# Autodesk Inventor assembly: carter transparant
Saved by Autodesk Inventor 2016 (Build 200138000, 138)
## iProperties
Created: 2013-10
Part Number: carter transparant
Material: Générique
Document SubType Name: Assembly
Designer: Bruno
Author: Bruno
Sending System: SolidWorks 2013
Last Author: christophe
Last Saved: 2014-02-15
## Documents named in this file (3)
- D:\Cours\Systèmes SI\Robot Haptique\Documentations_pedagogique\Modèle solidworks\Réel\carter transparant.iam
- D:\Cours\Systèmes SI\Robot Haptique\Documentations_pedagogique\Modèle solidworks\Réel\carter transparant.ipt
- D:\Cours\Systèmes SI\Robot Haptique\Documentations_pedagogique\Modèle solidworks\Réel\carter transparant2.ipt
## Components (3 placed, 2 different names)
1. carter transparant:1
2. carter transparant2:1
3. carter transparant:2
